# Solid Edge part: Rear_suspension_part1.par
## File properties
Author: KULL
Template: Iso Metric Part.par
Last saved by: KULL
Revision: 17
Application: Solid Edge
Accuracy: 0,990
Face Style: Model Default
Fill Style: Normal
Coef. of Thermal Exp: 0.0
Thermal Conductivity: 0.0
Specific Heat: 0.0
Modulus of Elasticity: 0.0
Poisson's Ratio: 0.0
Yield Stress: 0.0
Ultimate Stress: 0.0
Elongation: 0.0
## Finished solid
Body 1: solid body, 15 faces, 15 edges, 0 vertices, 2 separate solids.
  Faces by surface: cylinder 7, plane 5, torus 2, blend 1
  Edges by curve: circle 12, intersection 3
Bounding box of the edges (mm; curved faces can reach further): 45.000 x 18.250 x 20.458, from (-377.46, 40, 41.353) to (-332.46, 58.2501, 61.811).
Cylindrical faces by radius (mm): R2 x1, R2.5 x2, R3 x1, R5 x3
Toroidal faces (ring radius, tube radius in mm): R4.6 r0.4 x2
Planar faces by outward normal: +x 2, -x 2, oblique 1
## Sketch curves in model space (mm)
line (-367.46, 45, 56.811) -> (-367.46, 95.0907, -5.5243)
line (-342.46, 45, 56.811) -> (-342.46, 55.9117, 43.2319)
line (-363.195, 45, 56.811) -> (-320.4335, 45, 56.811)
line (-352.46, 45, 56.811) -> (-352.46, 83.2096, 9.2611)
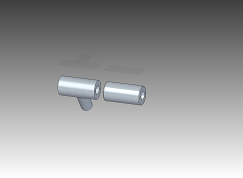
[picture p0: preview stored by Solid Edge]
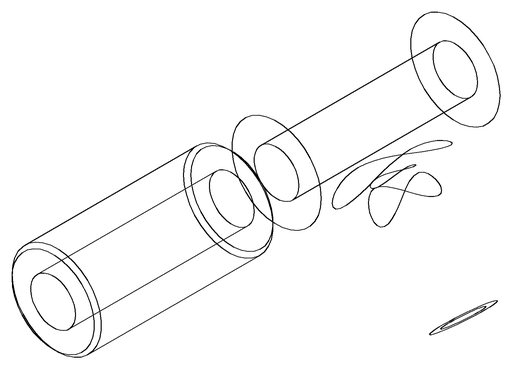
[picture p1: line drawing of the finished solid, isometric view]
